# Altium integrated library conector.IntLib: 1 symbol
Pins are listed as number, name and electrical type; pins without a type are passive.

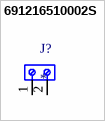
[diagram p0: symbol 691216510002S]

## 691216510002S
designator J?
2 Position Wire to Board Terminal Block Horizontal with Board 0.200 (5.08mm) Through Hole; MF: WÃ¼rth Elektronik; MP: 691216510002S
footprint 691216510002S
pins: 1, 2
